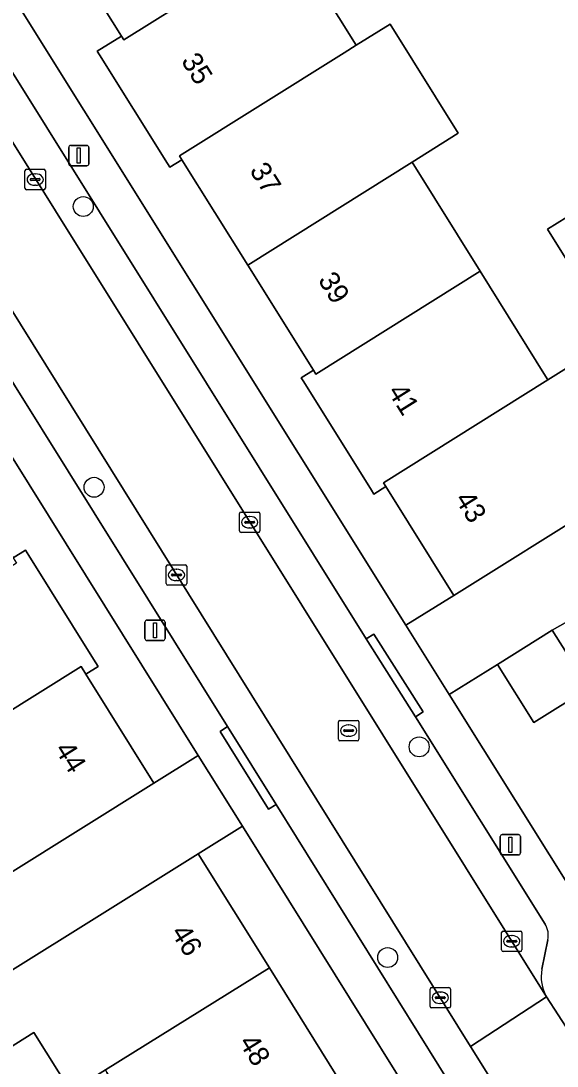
# Model space of a CAD drawing. Extents: x 159664 to 160323, y 385312 to 386115.
# Drawn here: x 159819.3 to 159845.6, y 385757.3 to 385808.6 of the extents above; entities that cross this region are included whole.
import ezdxf

# ---------------------------------------------------------------- set-up
doc = ezdxf.new("R2010")
doc.units = 0
for name, color, linetype in [('IMGEO_Boom', 7, 'Continuous'), ('IMGEO_Erf', 7, 'Continuous'), ('IMGEO_Kolk', 7, 'Continuous'), ('IMGEO_Lichtmast', 7, 'Continuous'), ('IMGEO_Pand', 7, 'Continuous'), ('IMGEO_Pand_nummerreeks', 7, 'Continuous'), ('IMGEO_Parkeervlak_open', 7, 'Continuous'), ('IMGEO_Rijbaan_lokaal_open', 7, 'Continuous'), ('IMGEO_Rioolput', 7, 'Continuous'), ('IMGEO_Voetpad_open', 7, 'Continuous')]:
    doc.layers.add(name, color=color, linetype=linetype)

msp = doc.modelspace()

# ---------------------------------------------------------------- linework, layer by layer
at = {"layer": 'IMGEO_Boom'}
for centre in [(159822.321, 385799.513), (159822.851, 385785.738), (159838.807, 385773.001), (159837.26, 385762.665)]:
    msp.add_circle(centre, 0.489, dxfattribs=at)
at = {"layer": 'IMGEO_Erf'}
for points in [[(159801.183, 385838.076), (159838.158, 385778.965), (159840.51, 385780.436), (159837.179, 385785.769), (159836.586, 385785.398), (159836.466, 385785.593), (159833.142, 385790.917), (159833.02, 385791.11), (159833.613, 385791.481), (159830.392, 385796.643), (159827.165, 385801.809), (159826.571, 385801.437), (159826.454, 385801.628), (159823.123, 385806.95), (159823.007, 385807.131), (159824.194, 385807.874), (159820.915, 385813.122)], [(159798.487, 385813.604), (159801.717, 385808.436), (159805.055, 385803.087), (159808.273, 385797.942), (159809.46, 385798.684), (159809.583, 385798.487), (159812.917, 385793.151), (159813.028, 385792.974), (159812.434, 385792.603), (159815.668, 385787.428), (159818.887, 385782.278), (159819.48, 385782.649), (159819.646, 385782.385), (159822.817, 385777.31), (159823.045, 385776.946), (159822.451, 385776.575), (159825.789, 385771.227), (159827.962, 385772.584), (159791.049, 385831.741)], [(159832.389, 385812.747), (159835.721, 385807.425), (159837.378, 385808.462), (159840.727, 385803.109), (159838.466, 385801.694), (159841.804, 385796.335), (159845.004, 385791.197), (159845.122, 385791.007), (159846.818, 385792.068)], [(159846.752, 385795.751), (159845.099, 385798.396), (159847.949, 385800.176)], [(159847.442, 385779.926), (159845.34, 385778.731), (159847.128, 385775.885), (159844.429, 385774.191), (159842.649, 385777.041), (159840.286, 385775.563), (159851.79, 385757.173)]]:
    msp.add_lwpolyline(points, dxfattribs=at)
for points in [[(159830.13, 385769.11), (159827.963, 385767.758), (159831.457, 385762.161), (159834.773, 385756.848), (159838.09, 385751.534), (159841.531, 385746.024), (159842.287, 385746.516), (159843.706, 385747.354)], [(159830.036, 385746.522), (159826.72, 385751.836), (159823.479, 385757.029), (159823.404, 385757.149), (159821.707, 385756.093), (159819.895, 385758.985), (159815.411, 385756.178), (159816.859, 385753.82), (159810.035, 385749.593), (159809.719, 385747.405), (159811.745, 385744.284), (159813.611, 385744.153), (159813.959, 385743.68), (159813.218, 385741.755), (159814.676, 385739.428), (159818.659, 385741.923), (159819.793, 385740.114), (159820.927, 385738.304), (159816.944, 385735.809), (159819.262, 385732.102), (159833.484, 385740.995)]]:
    msp.add_lwpolyline(points, close=True, dxfattribs=at)
at = {"layer": 'IMGEO_Kolk'}
for p, q in [((159819.46, 385800.412), (159819.46, 385801.264)), ((159819.535, 385801.338), (159820.387, 385801.338)), ((159820.461, 385801.264), (159820.461, 385800.412)), ((159819.719, 385800.832), (159819.719, 385800.844)), ((159820.157, 385800.795), (159819.759, 385800.795)), ((159819.762, 385800.881), (159820.16, 385800.881)), ((159819.948, 385801.118), (159819.973, 385801.118)), ((159820.203, 385800.844), (159820.203, 385800.832)), ((159820.387, 385800.338), (159819.535, 385800.338)), ((159819.971, 385800.558), (159819.946, 385800.558)), ((159829.989, 385783.596), (159829.989, 385784.448)), ((159830.064, 385784.522), (159830.916, 385784.522)), ((159830.477, 385784.302), (159830.502, 385784.302)), ((159830.99, 385784.448), (159830.99, 385783.596)), ((159830.248, 385784.016), (159830.248, 385784.028)), ((159830.686, 385783.979), (159830.288, 385783.979)), ((159830.291, 385784.065), (159830.689, 385784.065)), ((159830.5, 385783.742), (159830.475, 385783.742)), ((159830.732, 385784.028), (159830.732, 385784.016)), ((159830.916, 385783.522), (159830.064, 385783.522)), ((159826.396, 385781.011), (159826.396, 385781.863)), ((159826.471, 385781.937), (159827.323, 385781.937)), ((159826.884, 385781.717), (159826.909, 385781.717)), ((159827.397, 385781.863), (159827.397, 385781.011)), ((159826.655, 385781.431), (159826.655, 385781.443)), ((159827.093, 385781.394), (159826.695, 385781.394)), ((159826.698, 385781.48), (159827.096, 385781.48)), ((159826.907, 385781.157), (159826.882, 385781.157)), ((159827.139, 385781.443), (159827.139, 385781.431)), ((159827.323, 385780.937), (159826.471, 385780.937)), ((159842.851, 385763.037), (159842.851, 385763.889)), ((159842.926, 385763.963), (159843.778, 385763.963)), ((159843.339, 385763.743), (159843.364, 385763.743)), ((159843.852, 385763.889), (159843.852, 385763.037)), ((159843.11, 385763.457), (159843.11, 385763.469)), ((159843.548, 385763.42), (159843.15, 385763.42)), ((159843.153, 385763.506), (159843.551, 385763.506)), ((159843.362, 385763.183), (159843.337, 385763.183)), ((159843.594, 385763.469), (159843.594, 385763.457)), ((159843.778, 385762.963), (159842.926, 385762.963)), ((159839.417, 385761.19), (159840.269, 385761.19)), ((159839.342, 385760.264), (159839.342, 385761.116)), ((159839.601, 385760.684), (159839.601, 385760.696)), ((159840.039, 385760.647), (159839.641, 385760.647)), ((159839.644, 385760.733), (159840.042, 385760.733)), ((159839.83, 385760.97), (159839.855, 385760.97)), ((159840.085, 385760.696), (159840.085, 385760.684)), ((159840.343, 385761.116), (159840.343, 385760.264)), ((159840.269, 385760.19), (159839.417, 385760.19)), ((159839.853, 385760.41), (159839.828, 385760.41))]:
    msp.add_line(p, q, dxfattribs=at)
for points in [[(159819.46, 385800.412), (159819.46, 385801.264)], [(159819.535, 385801.338), (159820.387, 385801.338)], [(159820.461, 385801.264), (159820.461, 385800.412)], [(159820.387, 385800.338), (159819.535, 385800.338)], [(159829.989, 385783.596), (159829.989, 385784.448)], [(159830.064, 385784.522), (159830.916, 385784.522)], [(159830.99, 385784.448), (159830.99, 385783.596)], [(159830.916, 385783.522), (159830.064, 385783.522)], [(159826.396, 385781.011), (159826.396, 385781.863)], [(159826.471, 385781.937), (159827.323, 385781.937)], [(159827.397, 385781.863), (159827.397, 385781.011)], [(159827.323, 385780.937), (159826.471, 385780.937)], [(159842.851, 385763.037), (159842.851, 385763.889)], [(159842.926, 385763.963), (159843.778, 385763.963)], [(159843.852, 385763.889), (159843.852, 385763.037)], [(159843.778, 385762.963), (159842.926, 385762.963)], [(159839.417, 385761.19), (159840.269, 385761.19)], [(159839.342, 385760.264), (159839.342, 385761.116)], [(159840.343, 385761.116), (159840.343, 385760.264)], [(159840.269, 385760.19), (159839.417, 385760.19)]]:
    msp.add_lwpolyline(points, dxfattribs=at)
for centre, radius, start, end in [((159819.537, 385801.262), 0.0765, 91.552, 178.448), ((159819.537, 385801.262), 0.0765, 91.552, 178.448), ((159820.385, 385801.262), 0.0765, 1.552, 88.448), ((159820.385, 385801.262), 0.0765, 1.552, 88.448), ((159819.759, 385800.841), 0.0403, 85.8775, 175.7526), ((159819.756, 385800.831), 0.0366, 178.938, 274.7102), ((159820.16, 385800.838), 0.043, 264.8664, 352.4533), ((159820.164, 385800.843), 0.0386, 1.7309, 96.639), ((159819.537, 385800.414), 0.0765, 181.552, 268.448), ((159819.537, 385800.414), 0.0765, 181.552, 268.448), ((159820.385, 385800.414), 0.0765, 271.552, 358.448), ((159820.385, 385800.414), 0.0765, 271.552, 358.448), ((159830.066, 385784.446), 0.0765, 91.552, 178.448), ((159830.066, 385784.446), 0.0765, 91.552, 178.448), ((159830.914, 385784.446), 0.0765, 1.552, 88.448), ((159830.914, 385784.446), 0.0765, 1.552, 88.448), ((159830.288, 385784.025), 0.0403, 85.8775, 175.7526), ((159830.285, 385784.015), 0.0366, 178.938, 274.7102), ((159830.689, 385784.022), 0.043, 264.8664, 352.4533), ((159830.693, 385784.027), 0.0386, 1.7309, 96.639), ((159830.066, 385783.598), 0.0765, 181.552, 268.448), ((159830.066, 385783.598), 0.0765, 181.552, 268.448), ((159830.914, 385783.598), 0.0765, 271.552, 358.448), ((159830.914, 385783.598), 0.0765, 271.552, 358.448), ((159826.473, 385781.861), 0.0765, 91.552, 178.448), ((159826.473, 385781.861), 0.0765, 91.552, 178.448), ((159827.321, 385781.861), 0.0765, 1.552, 88.448), ((159827.321, 385781.861), 0.0765, 1.552, 88.448), ((159826.695, 385781.44), 0.0403, 85.8775, 175.7526), ((159826.692, 385781.43), 0.0366, 178.938, 274.7102), ((159827.096, 385781.437), 0.043, 264.8664, 352.4533), ((159827.1, 385781.442), 0.0386, 1.7309, 96.639), ((159826.473, 385781.013), 0.0765, 181.552, 268.448), ((159826.473, 385781.013), 0.0765, 181.552, 268.448), ((159827.321, 385781.013), 0.0765, 271.552, 358.448), ((159827.321, 385781.013), 0.0765, 271.552, 358.448), ((159842.928, 385763.887), 0.0765, 91.552, 178.448), ((159842.928, 385763.887), 0.0765, 91.552, 178.448), ((159843.776, 385763.887), 0.0765, 1.552, 88.448), ((159843.776, 385763.887), 0.0765, 1.552, 88.448), ((159843.15, 385763.466), 0.0403, 85.8775, 175.7526), ((159843.147, 385763.456), 0.0366, 178.938, 274.7102), ((159843.551, 385763.463), 0.043, 264.8664, 352.4533), ((159843.555, 385763.468), 0.0386, 1.7309, 96.639), ((159842.928, 385763.039), 0.0765, 181.552, 268.448), ((159842.928, 385763.039), 0.0765, 181.552, 268.448), ((159843.776, 385763.039), 0.0765, 271.552, 358.448), ((159843.776, 385763.039), 0.0765, 271.552, 358.448), ((159839.419, 385761.114), 0.0765, 91.552, 178.448), ((159839.419, 385761.114), 0.0765, 91.552, 178.448), ((159840.267, 385761.114), 0.0765, 1.552, 88.448), ((159840.267, 385761.114), 0.0765, 1.552, 88.448), ((159839.641, 385760.693), 0.0403, 85.8775, 175.7526), ((159839.638, 385760.683), 0.0366, 178.938, 274.7102), ((159840.042, 385760.69), 0.043, 264.8664, 352.4533), ((159840.046, 385760.695), 0.0386, 1.7309, 96.639), ((159839.419, 385760.266), 0.0765, 181.552, 268.448), ((159839.419, 385760.266), 0.0765, 181.552, 268.448), ((159840.267, 385760.266), 0.0765, 271.552, 358.448), ((159840.267, 385760.266), 0.0765, 271.552, 358.448)]:
    msp.add_arc(centre, radius, start, end, dxfattribs=at)
for centre, major_axis, ratio, start_param, end_param in [((159819.947, 385800.838), (-0.387, 0.002), 0.722429, 4.712389, 7.853982), ((159819.972, 385800.838), (-0.39, 0.002), 0.717154, 1.570796, 4.712389), ((159830.476, 385784.022), (-0.387, 0.002), 0.722429, 4.712389, 7.853982), ((159830.501, 385784.022), (-0.39, 0.002), 0.717154, 1.570796, 4.712389), ((159826.883, 385781.437), (-0.387, 0.002), 0.722429, 4.712389, 7.853982), ((159826.908, 385781.437), (-0.39, 0.002), 0.717154, 1.570796, 4.712389), ((159843.338, 385763.463), (-0.387, 0.002), 0.722429, 4.712389, 7.853982), ((159843.363, 385763.463), (-0.39, 0.002), 0.717154, 1.570796, 4.712389), ((159839.829, 385760.69), (-0.387, 0.002), 0.722429, 4.712389, 7.853982), ((159839.854, 385760.69), (-0.39, 0.002), 0.717154, 1.570796, 4.712389)]:
    msp.add_ellipse(centre, major_axis=major_axis, ratio=ratio, start_param=start_param, end_param=end_param, dxfattribs=at)
at = {"layer": 'IMGEO_Lichtmast'}
for p, q in [((159821.606, 385801.61), (159821.606, 385802.41)), ((159821.606, 385802.41), (159821.606, 385801.61)), ((159821.706, 385802.51), (159822.496, 385802.51)), ((159822.496, 385802.51), (159821.706, 385802.51)), ((159822.596, 385802.41), (159822.596, 385801.61)), ((159822.596, 385801.61), (159822.596, 385802.41)), ((159822.496, 385801.51), (159821.706, 385801.51)), ((159821.706, 385801.51), (159822.496, 385801.51)), ((159825.348, 385778.319), (159825.348, 385779.119)), ((159825.348, 385779.119), (159825.348, 385778.319)), ((159825.448, 385779.219), (159826.238, 385779.219)), ((159826.238, 385779.219), (159825.448, 385779.219)), ((159826.338, 385779.119), (159826.338, 385778.319)), ((159826.338, 385778.319), (159826.338, 385779.119)), ((159826.238, 385778.219), (159825.448, 385778.219)), ((159825.448, 385778.219), (159826.238, 385778.219)), ((159842.788, 385767.798), (159842.788, 385768.598)), ((159842.788, 385768.598), (159842.788, 385767.798)), ((159842.888, 385768.698), (159843.678, 385768.698)), ((159843.678, 385768.698), (159842.888, 385768.698)), ((159843.778, 385768.598), (159843.778, 385767.798)), ((159843.778, 385767.798), (159843.778, 385768.598)), ((159843.678, 385767.698), (159842.888, 385767.698)), ((159842.888, 385767.698), (159843.678, 385767.698))]:
    msp.add_line(p, q, dxfattribs=at)
for points in [[(159822.026, 385802.385), (159822.176, 385802.385), (159822.176, 385801.635), (159822.026, 385801.635), (159822.026, 385802.385)], [(159825.768, 385779.094), (159825.918, 385779.094), (159825.918, 385778.344), (159825.768, 385778.344), (159825.768, 385779.094)], [(159843.208, 385768.573), (159843.358, 385768.573), (159843.358, 385767.823), (159843.208, 385767.823), (159843.208, 385768.573)]]:
    msp.add_lwpolyline(points, dxfattribs=at)
for centre, start, end in [((159821.706, 385802.41), 90, 180), ((159821.706, 385802.41), 90, 180), ((159822.496, 385802.41), 0, 90), ((159822.496, 385802.41), 360, 90), ((159821.706, 385801.61), 180, 270), ((159821.706, 385801.61), 180, 270), ((159822.496, 385801.61), 270, 0), ((159822.496, 385801.61), 270, 0), ((159825.448, 385779.119), 90, 180), ((159825.448, 385779.119), 90, 180), ((159826.238, 385779.119), 0, 90), ((159826.238, 385779.119), 360, 90), ((159825.448, 385778.319), 180, 270), ((159825.448, 385778.319), 180, 270), ((159826.238, 385778.319), 270, 0), ((159826.238, 385778.319), 270, 0), ((159842.888, 385768.598), 90, 180), ((159842.888, 385768.598), 90, 180), ((159843.678, 385768.598), 0, 90), ((159843.678, 385768.598), 360, 90), ((159842.888, 385767.798), 180, 270), ((159842.888, 385767.798), 180, 270), ((159843.678, 385767.798), 270, 0), ((159843.678, 385767.798), 270, 0)]:
    msp.add_arc(centre, 0.1, start, end, dxfattribs=at)
at = {"layer": 'IMGEO_Pand'}
for points in [[(159832.389, 385812.747), (159828.989, 385818.173), (159820.915, 385813.122), (159824.194, 385807.874), (159824.308, 385807.691)], [(159835.721, 385807.425), (159832.389, 385812.747), (159824.308, 385807.691), (159824.194, 385807.874), (159823.007, 385807.131), (159823.123, 385806.95), (159826.454, 385801.628), (159826.571, 385801.437), (159827.165, 385801.809), (159827.047, 385801.999), (159835.128, 385807.054)], [(159835.721, 385807.425), (159835.128, 385807.054), (159827.047, 385801.999), (159827.165, 385801.809), (159830.392, 385796.643), (159838.466, 385801.694), (159840.727, 385803.109), (159837.378, 385808.462)], [(159841.804, 385796.335), (159838.466, 385801.694), (159830.392, 385796.643), (159833.613, 385791.481), (159833.734, 385791.287)], [(159849.602, 385797.531), (159847.949, 385800.176), (159845.099, 385798.396), (159846.752, 385795.751)], [(159845.122, 385791.007), (159845.004, 385791.197), (159841.804, 385796.335), (159833.734, 385791.287), (159833.613, 385791.481), (159833.02, 385791.11), (159833.142, 385790.917), (159836.466, 385785.593), (159836.586, 385785.398), (159837.179, 385785.769), (159837.058, 385785.963)], [(159854.746, 385789.325), (159853.065, 385792.024), (159848.583, 385789.233), (159846.818, 385792.068), (159845.122, 385791.007), (159837.058, 385785.963), (159837.179, 385785.769), (159840.51, 385780.436)], [(159822.817, 385777.31), (159819.646, 385782.385), (159819.48, 385782.649), (159818.887, 385782.278), (159819.052, 385782.014), (159810.983, 385776.98), (159814.159, 385771.908), (159822.223, 385776.94), (159822.451, 385776.575), (159823.045, 385776.946)], [(159847.128, 385775.885), (159845.34, 385778.731), (159842.649, 385777.041), (159844.429, 385774.191)], [(159825.789, 385771.227), (159822.451, 385776.575), (159822.223, 385776.94), (159814.159, 385771.908), (159812.463, 385770.845), (159814.352, 385767.828), (159809.877, 385765.026), (159811.56, 385762.339)], [(159831.457, 385762.161), (159827.963, 385767.758), (159813.729, 385758.865), (159815.411, 385756.178), (159819.895, 385758.985), (159821.707, 385756.093), (159823.404, 385757.149)], [(159831.457, 385762.161), (159823.404, 385757.149), (159823.479, 385757.029), (159826.72, 385751.836), (159834.773, 385756.848)]]:
    msp.add_lwpolyline(points, close=True, dxfattribs=at)
at = {"layer": 'IMGEO_Parkeervlak_open'}
for points in [[(159741.034, 385915.456), (159751.377, 385898.907), (159753.743, 385895.078), (159790.443, 385836.375), (159792.83, 385832.57), (159829.402, 385773.998), (159831.787, 385770.18), (159850.746, 385739.72), (159852.33, 385740.71), (159841.328, 385758.304), (159807.874, 385811.971), (159785.139, 385848.258)], [(159788.888, 385850.614), (159845.062, 385760.744)], [(159836.21, 385778.296), (159799.599, 385836.908)], [(159838.62, 385774.468), (159836.21, 385778.296)], [(159844.984, 385764.305), (159838.62, 385774.468)], [(159844.833, 385762.088), (159845.116, 385763.533)]]:
    msp.add_lwpolyline(points, dxfattribs=at)
for centre, radius, start, end in [((159844.204, 385763.774), 0.943, 345.1657, 34.24), ((159846.685, 385761.712), 1.89, 168.5231, 210.8161)]:
    msp.add_arc(centre, radius, start, end, dxfattribs=at)
at = {"layer": 'IMGEO_Rijbaan_lokaal_open'}
msp.add_lwpolyline([(159788.888, 385850.614), (159785.139, 385848.258), (159807.874, 385811.971), (159841.328, 385758.304), (159845.062, 385760.744)], close=True, dxfattribs=at)
msp.add_lwpolyline([(159847.352, 385757.199), (159845.062, 385760.744), (159841.328, 385758.304), (159852.33, 385740.71), (159853.294, 385739.117), (159857.224, 385741.538), (159855.349, 385744.522)], dxfattribs=at)
at = {"layer": 'IMGEO_Rioolput'}
for p, q in [((159834.843, 385773.372), (159834.843, 385774.224)), ((159834.918, 385774.298), (159835.77, 385774.298)), ((159835.331, 385774.078), (159835.356, 385774.078)), ((159835.844, 385774.224), (159835.844, 385773.372)), ((159835.102, 385773.792), (159835.102, 385773.804)), ((159835.54, 385773.755), (159835.142, 385773.755)), ((159835.145, 385773.841), (159835.543, 385773.841)), ((159835.354, 385773.518), (159835.329, 385773.518)), ((159835.586, 385773.804), (159835.586, 385773.792)), ((159835.77, 385773.298), (159834.918, 385773.298))]:
    msp.add_line(p, q, dxfattribs=at)
for points in [[(159834.843, 385773.372), (159834.843, 385774.224)], [(159834.918, 385774.298), (159835.77, 385774.298)], [(159835.844, 385774.224), (159835.844, 385773.372)], [(159835.77, 385773.298), (159834.918, 385773.298)]]:
    msp.add_lwpolyline(points, dxfattribs=at)
for centre, radius, start, end in [((159834.92, 385774.222), 0.0765, 91.552, 178.448), ((159834.92, 385774.222), 0.0765, 91.552, 178.448), ((159835.768, 385774.222), 0.0765, 1.552, 88.448), ((159835.768, 385774.222), 0.0765, 1.552, 88.448), ((159835.142, 385773.801), 0.0403, 85.8775, 175.7526), ((159835.139, 385773.791), 0.0366, 178.938, 274.7102), ((159835.543, 385773.798), 0.043, 264.8664, 352.4533), ((159835.547, 385773.803), 0.0386, 1.7309, 96.639), ((159834.92, 385773.374), 0.0765, 181.552, 268.448), ((159834.92, 385773.374), 0.0765, 181.552, 268.448), ((159835.768, 385773.374), 0.0765, 271.552, 358.448), ((159835.768, 385773.374), 0.0765, 271.552, 358.448)]:
    msp.add_arc(centre, radius, start, end, dxfattribs=at)
for centre, major_axis, ratio, start_param, end_param in [((159835.33, 385773.798), (-0.387, 0.002), 0.722429, 4.712389, 7.853982), ((159835.355, 385773.798), (-0.39, 0.002), 0.717154, 1.570796, 4.712389)]:
    msp.add_ellipse(centre, major_axis=major_axis, ratio=ratio, start_param=start_param, end_param=end_param, dxfattribs=at)
at = {"layer": 'IMGEO_Voetpad_open'}
for points in [[(159747.851, 385919.727), (159758.184, 385903.198), (159758.579, 385903.421), (159760.952, 385899.606), (159760.579, 385899.376), (159797.238, 385840.688), (159797.62, 385840.926), (159799.98, 385837.147), (159799.599, 385836.908), (159836.21, 385778.296), (159836.589, 385778.536), (159839.001, 385774.716), (159838.62, 385774.468), (159844.984, 385764.305)], [(159741.032, 385918.933), (159740.787, 385919.315), (159737.177, 385917.789), (159749.768, 385897.575), (159749.851, 385897.63), (159751.956, 385894.264), (159788.93, 385835.134), (159789.958, 385833.49), (159791.049, 385831.741), (159827.962, 385772.584), (159830.13, 385769.11), (159843.706, 385747.354)], [(159850.746, 385739.72), (159831.787, 385770.18), (159831.417, 385769.944), (159829.035, 385773.762), (159829.402, 385773.998), (159792.83, 385832.57), (159792.452, 385832.313), (159790.073, 385836.148), (159790.443, 385836.375), (159753.743, 385895.078), (159753.361, 385894.84), (159750.98, 385898.656), (159751.377, 385898.907), (159741.034, 385915.456)], [(159848.849, 385755.329), (159851.79, 385757.173), (159840.286, 385775.563), (159838.158, 385778.965), (159801.183, 385838.076)], [(159854.746, 385789.325), (159840.51, 385780.436), (159838.158, 385778.965), (159840.286, 385775.563), (159842.649, 385777.041), (159845.34, 385778.731), (159847.442, 385779.926)], [(159813.729, 385758.865), (159827.963, 385767.758), (159830.13, 385769.11), (159827.962, 385772.584), (159825.789, 385771.227), (159811.56, 385762.339)], [(159845.116, 385763.533), (159844.833, 385762.088)], [(159845.062, 385760.744), (159847.352, 385757.199)]]:
    msp.add_lwpolyline(points, dxfattribs=at)
for points in [[(159838.62, 385774.468), (159839.001, 385774.716), (159836.589, 385778.536), (159836.21, 385778.296)], [(159829.402, 385773.998), (159829.035, 385773.762), (159831.417, 385769.944), (159831.787, 385770.18)]]:
    msp.add_lwpolyline(points, close=True, dxfattribs=at)
for centre, radius, start, end in [((159844.204, 385763.774), 0.943, 345.1657, 34.24), ((159846.685, 385761.712), 1.89, 168.5231, 210.8161)]:
    msp.add_arc(centre, radius, start, end, dxfattribs=at)

# ---------------------------------------------------------------- texts
at = {"layer": 'IMGEO_Pand_nummerreeks'}
for s, rotation, p in [('35', 301.9995, (159827.097, 385806.658)), ('37', 301.9995, (159830.457, 385801.283)), ('39', 301.9995, (159833.816, 385795.907)), ('41', 301.9995, (159837.235, 385790.435)), ('43', 301.9995, (159840.535, 385785.156)), ('44', 301.988, (159820.892, 385772.879)), ('46', 301.7531, (159826.595, 385763.897)), ('48', 301.7531, (159829.931, 385758.507))]:
    msp.add_text(s, height=1, rotation=rotation, dxfattribs=at).set_placement(p)

doc.saveas('drawing.dxf')
